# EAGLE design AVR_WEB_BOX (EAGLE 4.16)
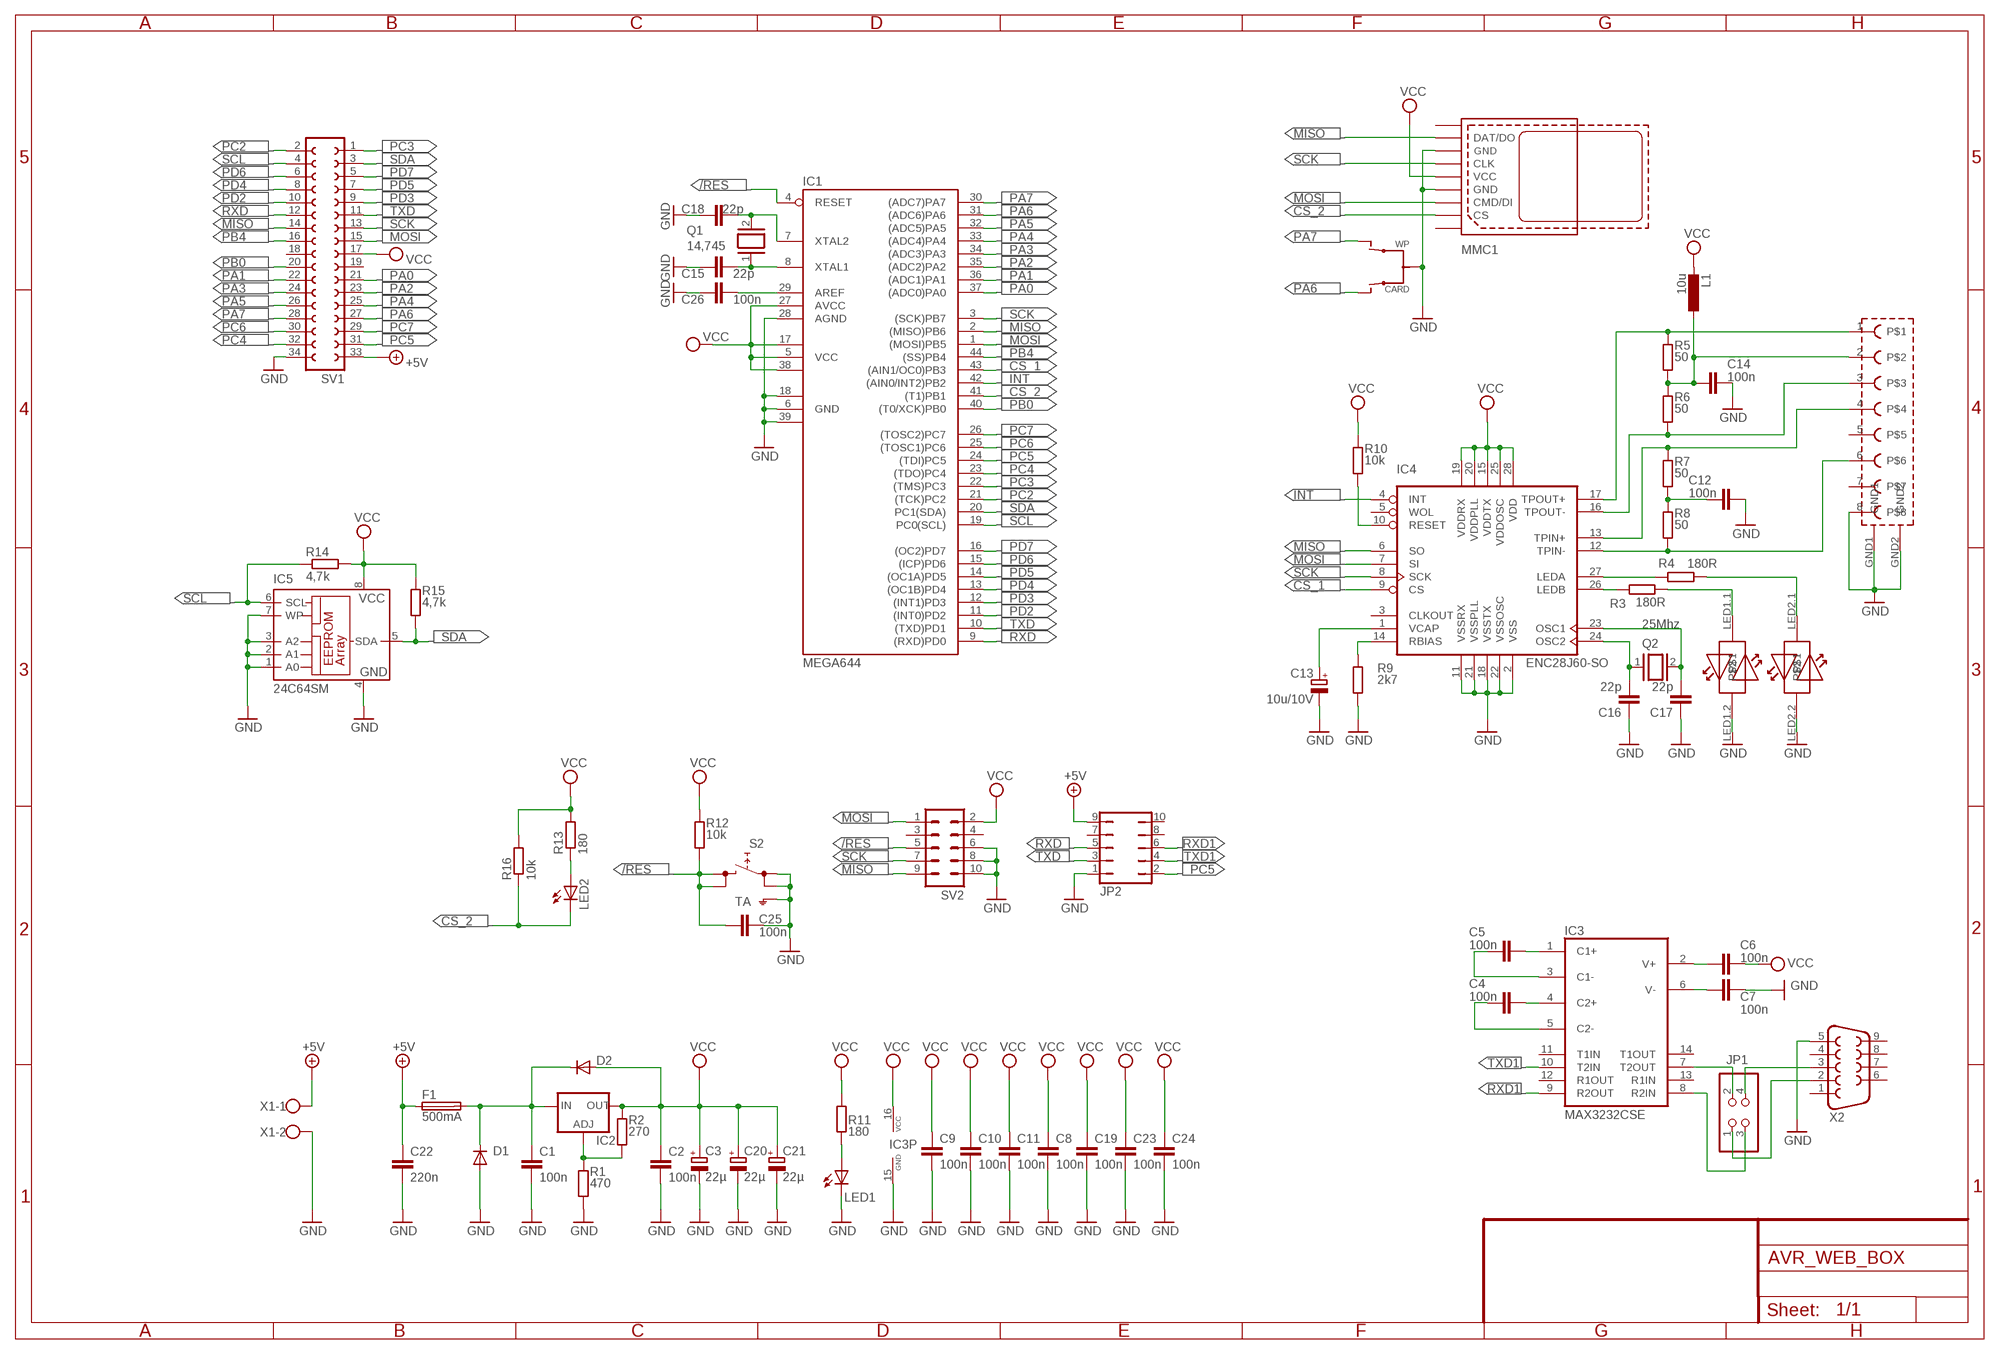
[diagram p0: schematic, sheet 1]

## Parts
C1  100n  C-EUC0805  [C0805]
C2  100n  C-EUC0805  [C0805]
C3  22µ  CPOL-EUSMCE  [SMC_E]
C4  100n  C-EUC0805  [C0805]
C5  100n  C-EUC0805  [C0805]
C6  100n  C-EUC0805  [C0805]
C7  100n  C-EUC0805  [C0805]
C8  100n  C-EUC0805  [C0805]
C9  100n  C-EUC0805  [C0805]
C10  100n  C-EUC0805  [C0805]
C11  100n  C-EUC0805  [C0805]
C12  100n  C-EUC0805  [C0805]
C13  10u/10V  CPOL-EUSMCA  [SMC_A]
C14  100n  C-EUC0805  [C0805]
C15  22p  C-EUC0805  [C0805]
C16  22p  C-EUC0805  [C0805]
C17  22p  C-EUC0805  [C0805]
C18  22p  C-EUC0805  [C0805]
C19  100n  C-EUC0805  [C0805]
C20  22µ  CPOL-EUSMCE  [SMC_E]
C21  22µ  CPOL-EUSMCE  [SMC_E]
C22  220n  C-EUC0805  [C0805]
C23  100n  C-EUC0805  [C0805]
C24  100n  C-EUC0805  [C0805]
C25  100n  C-EUC0805  [C0805]
C26  100n  C-EUC0805  [C0805]
D1  DIODE-SMB  [SMB]
D2  DIODE-SMB  [SMB]
F1  500mA  PICOFUSE  [PICOFUSE]
IC1  MEGA644  MEGA32-A  [TQFP44]
IC2  LM317TL  [317TL]
IC3  MAX3232CSE  [SO16]
IC4  ENC28J60-SO  [SO28W]
IC5  24C64SM  [SO-08M]
JP1  PINHD-2X2  [2X02]
JP2  JP5Q  [JP5Q]
L1  10u  L-EU0207/10  [0207/10]
LED1  LEDCHIP-LED0805  [CHIP-LED0805]
LED2  LEDCHIP-LED0805  [CHIP-LED0805]
MMC1  SD_CARD  [SD9]
Q1  14,745  XTAL/S  [QS]
Q2  25Mhz  XTAL/S  [QS]
R1  470  R-EU_M0805  [M0805]
R2  270  R-EU_M0805  [M0805]
R3  180R  R-EU_R0805  [R0805]
R4  180R  R-EU_R0805  [R0805]
R5  50  R-EU_R0805  [R0805]
R6  50  R-EU_R0805  [R0805]
R7  50  R-EU_R0805  [R0805]
R8  50  R-EU_R0805  [R0805]
R9  2k7  R-EU_R0805  [R0805]
R10  10k  R-EU_R0805  [R0805]
R11  180  R-EU_M0805  [M0805]
R12  10k  R-EU_M0805  [M0805]
R13  180  R-EU_M0805  [M0805]
R14  4,7k  R-EU_R0805  [R0805]
R15  4,7k  R-EU_R0805  [R0805]
R16  10k  R-EU_M0805  [M0805]
S2  TA  SKHMPSE010  [SKHMPXE010]
SV1  FE17-2W  [FE17-2W]
SV2  ML10L  [ML10L]
U$1  MAGJACK  [MAGJACK]
X1  W237-02P  [W237-132]
X2  F09HP  [F09HP]

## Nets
+5V: C22.1 F1.1 JP2.9 SV1.33 X1.1
/RES: C25.2 IC1.4(RESET) R12.1 S2.3(2.1) S2.4(2.2) SV2.5
CS_1: IC1.43((AIN1/OC0)PB3) IC4.9(CS)
CS_2: IC1.41((T1)PB1) LED2.C MMC1.7(CS) R16.1
GND: C1.2 C2.2 C3.- C7.2 C8.2 C9.2 C10.2 C11.2 C12.2 C13.- C14.2 C15.1 C16.1 C17.1 C18.1 C19.2 C20.- C21.- C22.2 C23.2 C24.2 C25.1 C26.1 D1.A IC1.6(GND) IC1.18(GND1) IC1.28(AGND) IC1.39(GND2) IC3.15(GND) IC4.2(VSS) IC4.11(VSSRX) IC4.18(VSSTX) IC4.21(VSSPLL) IC4.22(VSSOSC) IC5.1(A0) IC5.2(A1) IC5.3(A2) IC5.4(GND) IC5.7(WP) JP2.1 LED1.C MMC1.2(GND) MMC1.5(GND1) MMC1.SW1 R1.1 R9.1 S2.1(1.1) S2.2(1.2) S2.5(SH) SV1.34 SV2.6 SV2.8 SV2.10 U$1.8 U$1.GND1 U$1.GND2 U$1.LED1.2 U$1.LED2.2 X1.2 X2.5
INT: IC1.42((AIN0/INT2)PB2) IC4.4(INT)
MISO: IC1.2((MISO)PB6) IC4.6(SO) MMC1.1(DAT/DO) SV1.14 SV2.9
MOSI: IC1.1((MOSI)PB5) IC4.7(SI) MMC1.6(CMD/DI) SV1.15 SV2.1
N$1: C15.2 IC1.8(XTAL1) Q1.1
N$2: C18.2 IC1.7(XTAL2) Q1.2
N$3: C16.2 IC4.24(OSC2) Q2.1
N$5: C14.1 L1.1 R5.1 R6.2 U$1.2
N$8: LED1.A R11.1
N$9: C13.+ IC4.1(VCAP)
N$10: IC4.14(RBIAS) R9.2
N$11: C17.2 IC4.23(OSC1) Q2.2
N$12: IC2.1(ADJ) R1.2 R2.1
N$13: LED2.A R13.1
N$14: IC4.27(LEDA) R4.1
N$16: C26.2 IC1.29(AREF)
N$33: IC4.26(LEDB) R3.1
N$36: R4.2 U$1.LED2.1
N$37: IC4.10(RESET) R10.2
N$39: R3.2 U$1.LED1.1
N$40: JP1.1 X2.2
N$41: C12.1 R7.1 R8.2
N$42: IC4.12(TPIN-) R8.1 U$1.6
N$43: IC4.13(TPIN+) R7.2 U$1.4
N$44: IC4.16(TPOUT-) R6.1 U$1.3
N$45: IC4.17(TPOUT+) R5.2 U$1.1
N$49: JP1.4 X2.3
N$50: IC3.8(R2IN) JP1.3
N$51: IC3.7(T2OUT) JP1.2
N$52: C4.2 IC3.4(C2+)
N$53: C4.1 IC3.5(C2-)
N$56: C5.1 IC3.3(C1-)
N$57: C5.2 IC3.1(C1+)
N$58: C6.1 IC3.2(V+)
N$59: C7.1 IC3.6(V-)
N$250: C1.1 D1.C D2.C F1.2 IC2.3(IN)
PA0: IC1.37((ADC0)PA0) SV1.21
PA1: IC1.36((ADC1)PA1) SV1.22
PA2: IC1.35((ADC2)PA2) SV1.23
PA3: IC1.34((ADC3)PA3) SV1.24
PA4: IC1.33((ADC4)PA4) SV1.25
PA5: IC1.32((ADC5)PA5) SV1.26
PA6: IC1.31((ADC6)PA6) MMC1.SW3 SV1.27
PA7: IC1.30((ADC7)PA7) MMC1.SW2 SV1.28
PB0: IC1.40((T0/XCK)PB0) SV1.20
PB4: IC1.44((SS)PB4) SV1.16
PC2: IC1.21((TCK)PC2) SV1.2
PC3: IC1.22((TMS)PC3) SV1.1
PC4: IC1.23((TDO)PC4) SV1.32
PC5: IC1.24((TDI)PC5) JP2.2 SV1.31
PC6: IC1.25((TOSC1)PC6) SV1.30
PC7: IC1.26((TOSC2)PC7) SV1.29
PD2: IC1.11((INT0)PD2) SV1.10
PD3: IC1.12((INT1)PD3) SV1.9
PD4: IC1.13((OC1B)PD4) SV1.8
PD5: IC1.14((OC1A)PD5) SV1.7
PD6: IC1.15((ICP)PD6) SV1.6
PD7: IC1.16((OC2)PD7) SV1.5
RXD: IC1.9((RXD)PD0) JP2.5 SV1.12
RXD1: IC3.9(R2OUT) JP2.6
SCK: IC1.3((SCK)PB7) IC4.8(SCK) MMC1.3(CLK) SV1.13 SV2.7
SCL: IC1.19(PC0(SCL)) IC5.6(SCL) R14.1 SV1.4
SDA: IC1.20(PC1(SDA)) IC5.5(SDA) R15.1 SV1.3
TXD: IC1.10((TXD)PD1) JP2.3 SV1.11
TXD1: IC3.10(T2IN) JP2.4
VCC: C2.1 C3.+ C6.2 C8.1 C9.1 C10.1 C11.1 C19.1 C20.+ C21.+ C23.1 C24.1 D2.A IC1.5(VCC) IC1.17(VCC1) IC1.27(AVCC) IC1.38(VCC2) IC2.2(OUT) IC3.16(VCC) IC4.15(VDDTX) IC4.19(VDDRX) IC4.20(VDDPLL) IC4.25(VDDOSC) IC4.28(VDD) IC5.8(VCC) L1.2 MMC1.4(VCC) R2.2 R10.1 R11.2 R12.2 R13.2 R14.2 R15.2 R16.2 SV1.17 SV2.2
Unconnected: IC3.11(T1IN) IC3.12(R1OUT) IC3.13(R1IN) IC3.14(T1OUT) IC4.3(CLKOUT) IC4.5(WOL) JP2.7 JP2.8 JP2.10 MMC1.8(DAT1/RSV:8) MMC1.9(DAT2/RSV:9) SV1.18 SV1.19 SV2.3 SV2.4 U$1.5 U$1.7 X2.1 X2.4 X2.6 X2.7 X2.8 X2.9

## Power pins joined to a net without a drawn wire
GND1: MMC1.G1(GND1)
GND2: MMC1.G2(GND2)
GND3: MMC1.G3(GND3)
GND4: MMC1.G4(GND4)
GND5: MMC1.G5(GND5)
GND6: MMC1.G6(GND6)
GND7: MMC1.G7(GND7)

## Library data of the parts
C1 C2 C4-C12 C14-C19 C22-C26 = rcl:C-EU: CAPACITOR, European symbol
C3 C13 C20 C21 = rcl:CPOL-EU: POLARIZED CAPACITOR, European symbol
D1 D2 = diode:DIODE-: DIODE
F1 = fuse:PICOFUSE: PICOFUSE
IC1 = avr:MEGA32: MICROCONTROLLER 32 Kbytes FLASH 2 Kbytes SRAM 1 Kbytes EEPROM USART 8-channel 10 bit ADC
IC2 = v-reg:LM317TL: VOLTAGE REGULATOR
IC3 = maxim:MAX3232*: True RS-232 Transceivers 3.0V to 5.5V, Low-Power up to 1Mbps, Using Four 0.1µF External Capacitors Source: http://pdfserv.maxim-ic.com/en/ds/MAX3222-MAX3241.pdf
IC4 = microchip-enc28j60:ENC28J60-*: Microchip 10Mbit Eth. contoller with SPI interface
IC5 = microchip:24*: Serial EEPROM I2C
JP1 = pinhead:PINHD-2X2: PIN HEADER
JP2 = jumper:JP5Q: JUMPER
L1 = rcl:L-EU: INDUCTOR, European symbol
LED1 LED2 = led:LED: LED
MMC1 = sd_card:SD_CARD: Farnell / Order Code: 4381610 http://www.farnell.com/datasheets/37839.pdf kingfont Precision Industrial co., LTD. Secure Digital Memory Card Push-Push connector type B Changes by Guido Fischer - 29.12.2004 www.ispf.de by André Mansur - Brazil - 19/11/2004
Q1 Q2 = special:XTAL/S: CRYSTAL
R1-R16 = rcl:R-EU_: RESISTOR, European symbol
S2 = switch:SKHMP*E010: 6.2 X 6.5mm TACT Switch (SMD) Source: http://www3.alps.co.jp/WebObjects/catalog.woa/PDF/E/Switch/Tact/SKHM/SKHM.PDF
SV1 = con-lsta:FE17-2W: FEMALE HEADER
SV2 = con-harting-ml:ML10: HARTING
U$1 = magjacksmalldrill:MAGJACK
X1 = con-wago-508:W237-02P: WAGO SREW CLAMP
X2 = con-subd:F09: SUB-D

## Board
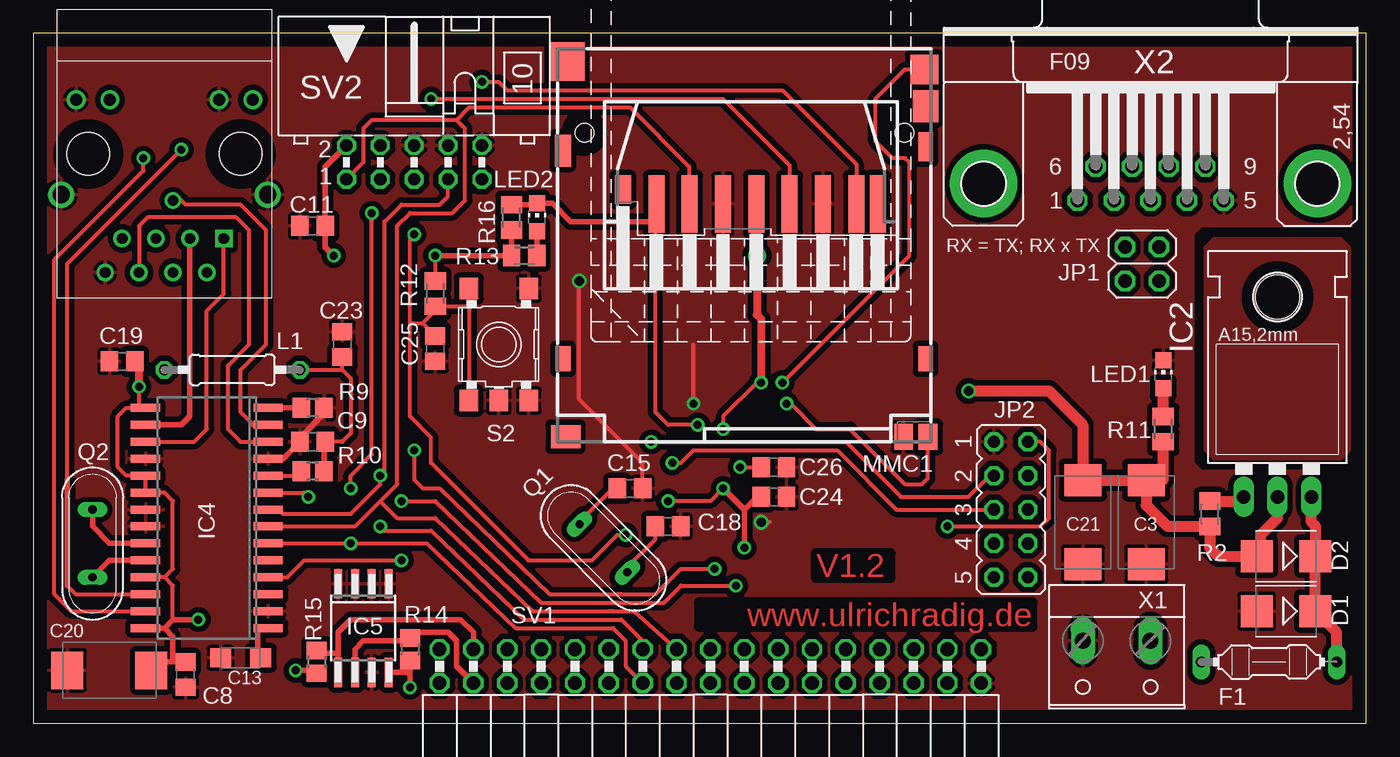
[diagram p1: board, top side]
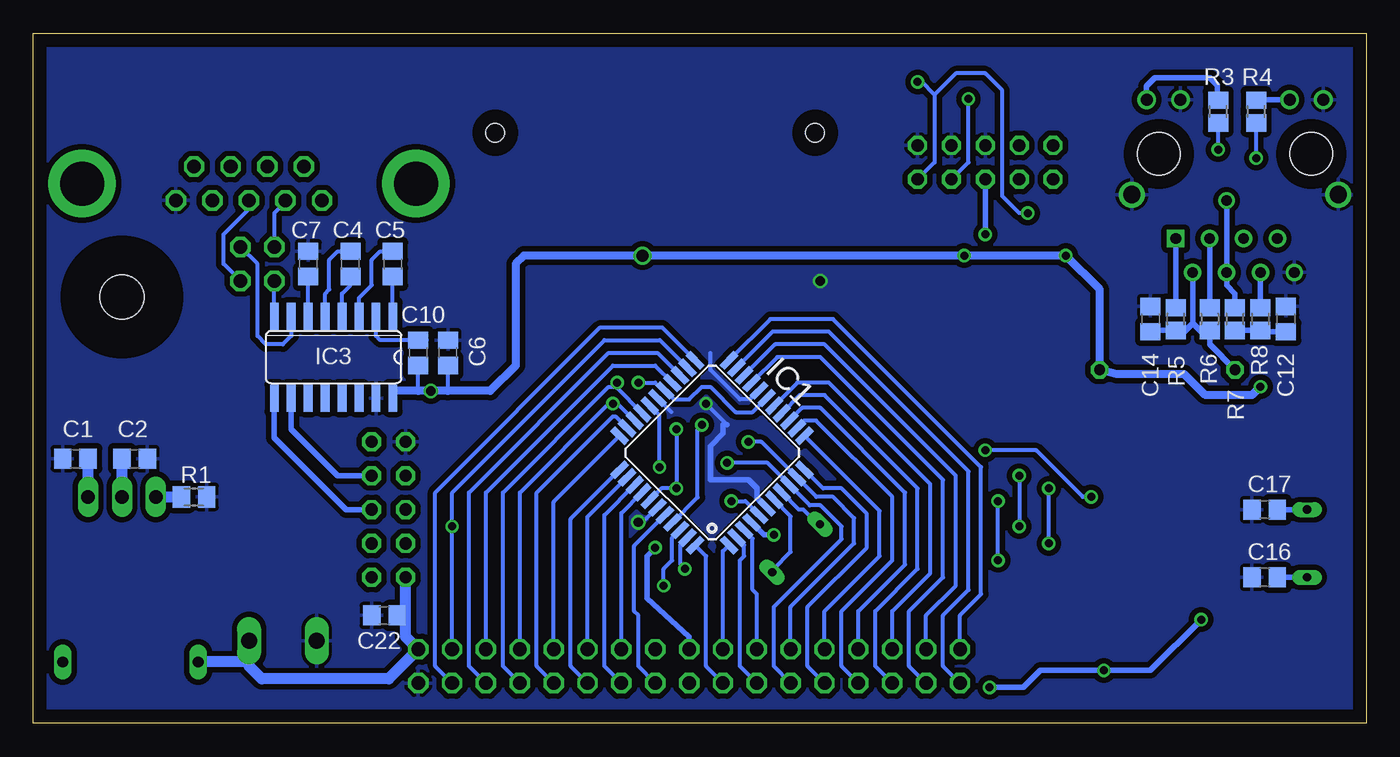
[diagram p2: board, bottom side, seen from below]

Size 99.99 x 51.74 mm. Coordinates in mm from the lower left corner, seen from the top.
Outline: 0,0 99.99,0 99.99,51.74 0,51.74 0,0
Copper layers (1*16): Top 0.035mm / dielectric 1.5mm / Bottom 0.035mm
Design rules "default": minimum track width 10mil, minimum drill 24mil, track to track 8mil, track to pad 8mil, pad to pad 8mil, via to via 8mil, smd to smd 8mil, copper to edge 40mil, drill to drill 8mil, minimum pad ring 10mil, minimum via ring 8mil, stop-mask expansion 4mil, vias tented up to drill 0mil, thermal gap 10mil

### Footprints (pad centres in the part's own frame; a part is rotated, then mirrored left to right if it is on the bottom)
C0805 = smd 1.3 x 1.5: 1 -0.95,0; 2 0.95,0
SMC_E = smd 2.4 x 2.8: + -3.15,0; - 3.15,0
SMC_A = smd 1.6 x 1.4: + -1.5,0; - 1.5,0
SMB = smd 2.4 x 2.4: A 2.2,0; C -2.2,0
PICOFUSE = drill 0.813 long: 1 -5.08,0; 2 5.08,0
TQFP44 = smd 1.5 x 0.5: 1 -5.8,4; 2 -5.8,3.2; 3 -5.8,2.4; 4 -5.8,1.6; 5 -5.8,0.8; 6 -5.8,0; 7 -5.8,-0.8; 8 -5.8,-1.6; 9 -5.8,-2.4; 10 -5.8,-3.2; 11 -5.8,-4; 23 5.8,-4; 24 5.8,-3.2; 25 5.8,-2.4; 26 5.8,-1.6; 27 5.8,-0.8; 28 5.8,0; 29 5.8,0.8; 30 5.8,1.6; 31 5.8,2.4; 32 5.8,3.2; 33 5.8,4 | smd 0.5 x 1.5: 12 -4,-5.8; 13 -3.2,-5.8; 14 -2.4,-5.8; 15 -1.6,-5.8; 16 -0.8,-5.8; 17 0,-5.8; 18 0.8,-5.8; 19 1.6,-5.8; 20 2.4,-5.8; 21 3.2,-5.8; 22 4,-5.8; 34 4,5.8; 35 3.2,5.8; 36 2.4,5.8; 37 1.6,5.8; 38 0.8,5.8; 39 0,5.8; 40 -0.8,5.8; 41 -1.6,5.8; 42 -2.4,5.8; 43 -3.2,5.8; 44 -4,5.8
317TL = drill 1.016 long: 1 -2.54,-3.81; 2 0,-3.81; 3 2.54,-3.81 | hole 3.302: 0,11.176
SO16 = smd 0.66 x 2.032: 1 -4.445,-3.073; 2 -3.175,-3.073; 3 -1.905,-3.073; 4 -0.635,-3.073; 5 0.635,-3.073; 6 1.905,-3.073; 7 3.175,-3.073; 8 4.445,-3.073; 9 4.445,3.073; 10 3.175,3.073; 11 1.905,3.073; 12 0.635,3.073; 13 -0.635,3.073; 14 -1.905,3.073; 15 -3.175,3.073; 16 -4.445,3.073
SO28W = smd 0.6 x 2.2: 1 -8.255,-4.6; 2 -6.985,-4.6; 3 -5.715,-4.6; 4 -4.445,-4.6; 5 -3.175,-4.6; 6 -1.905,-4.6; 7 -0.635,-4.6; 8 0.635,-4.6; 9 1.905,-4.6; 10 3.175,-4.6; 11 4.445,-4.6; 12 5.715,-4.6; 13 6.985,-4.6; 14 8.255,-4.6; 15 8.255,4.6; 16 6.985,4.6; 17 5.715,4.6; 18 4.445,4.6; 19 3.175,4.6; 20 1.905,4.6; 21 0.635,4.6; 22 -0.635,4.6; 23 -1.905,4.6; 24 -3.175,4.6; 25 -4.445,4.6; 26 -5.715,4.6; 27 -6.985,4.6; 28 -8.255,4.6
SO-08M = smd 0.6 x 2.2: 1 -1.905,-3.33; 2 -0.635,-3.33; 3 0.635,-3.33; 4 1.905,-3.33; 5 1.905,3.33; 6 0.635,3.33; 7 -0.635,3.33; 8 -1.905,3.33
2X02 = drill 1.016 octagon: 1 -1.27,-1.27; 2 -1.27,1.27; 3 1.27,-1.27; 4 1.27,1.27
JP5Q = drill 0.914 octagon: 1 -5.08,-1.27; 2 -5.08,1.27; 3 -2.54,-1.27; 4 -2.54,1.27; 5 0,-1.27; 6 0,1.27; 7 2.54,-1.27; 8 2.54,1.27; 9 5.08,-1.27; 10 5.08,1.27
0207/10 = drill 0.813 octagon: 1 -5.08,0; 2 5.08,0
CHIP-LED0805 = smd 1.2 x 1.2: A 0,-1.05; C 0,1.05
SD9 = smd 1.2 x 4.3: 1 -8.4,5.34; 2 -5.9,5.34; 3 -3.4,5.34; 4 -0.9,5.34; 5 1.6,5.34; 6 4.1,5.34; 7 6.6,5.34; 8 -10.025,5.34 | smd 1.2 x 2.15: 9 9.1,4.265 | smd 1.9 x 2.4: G1 -13.6,-2 | smd 1.1 x 2.2: G2 -13.6,1.05 | smd 1.1 x 1.9: G3 -13.6,16.95; G5 13.6,16.95 | smd 2.2 x 1.75: G4 13.4,22.8 | smd 1.2 x 2.4: G6 13.6,1.35 | smd 2.6 x 2.9: G7 13.3,-5.35 | smd 1.4 x 1.95: SW1 -11.95,22.8 | smd 2.1 x 2.2: SW2 -13.5,-4.75 | smd 1.45 x 1.95: SW3 -13.775,22.8 | hole 1.4: -12,0; 12,0
QS = drill 0.61 long: 1 -2.54,0; 2 2.54,0
M0805 = smd 1.3 x 1.6: 1 -0.95,0; 2 0.95,0
R0805 = smd 1.3 x 1.5: 1 -0.85,0; 2 0.85,0
SKHMPXE010 = smd 1.6 x 1.4: 1 -4.2,2.25; 2 4.2,2.25; 3 -4.2,-2.25; 4 4.2,-2.25; 5 4.2,0
FE17-2W = drill 1.016 octagon: 1 -20.32,1.27; 2 -20.32,-1.27; 3 -17.78,1.27; 4 -17.78,-1.27; 5 -15.24,1.27; 6 -15.24,-1.27; 7 -12.7,1.27; 8 -12.7,-1.27; 9 -10.16,1.27; 10 -10.16,-1.27; 11 -7.62,1.27; 12 -7.62,-1.27; 13 -5.08,1.27; 14 -5.08,-1.27; 15 -2.54,1.27; 16 -2.54,-1.27; 17 0,1.27; 18 0,-1.27; 19 2.54,1.27; 20 2.54,-1.27; 21 5.08,1.27; 22 5.08,-1.27; 23 7.62,1.27; 24 7.62,-1.27; 25 10.16,1.27; 26 10.16,-1.27; 27 12.7,1.27; 28 12.7,-1.27; 29 15.24,1.27; 30 15.24,-1.27; 31 17.78,1.27; 32 17.78,-1.27; 33 20.32,1.27; 34 20.32,-1.27
ML10L = drill 0.914 octagon: 1 -5.08,-1.27; 2 -5.08,1.27; 3 -2.54,-1.27; 4 -2.54,1.27; 5 0,-1.27; 6 0,1.27; 7 2.54,-1.27; 8 2.54,1.27; 9 5.08,-1.27; 10 5.08,1.27
MAGJACK = drill 0.8 square: 1 -4.445,6.35 | drill 0.8 round: 2 -3.175,8.89; 3 -1.905,6.35; 4 -0.635,8.89; 5 0.635,6.35; 6 1.905,8.89; 7 3.175,6.35; 8 4.445,8.89 | drill 1.3 round: GND1 -7.747,3.048; GND2 7.747,3.048 | drill 0.9 round: LED1.1 -6.629,-4.064; LED1.2 -4.089,-4.064; LED2.1 4.089,-4.064; LED2.2 6.629,-4.064 | hole 3.2: -5.715,0; 5.715,0
W237-132 = drill 1.194 long: 1 -2.54,-0.635; 2 2.54,-0.635
F09HP = drill 1.016 octagon: 1 -5.486,-1.27; 2 -2.743,-1.27; 3 0,-1.27; 4 2.743,-1.27; 5 5.486,-1.27; 6 -4.115,1.27; 7 -1.372,1.27; 8 1.372,1.27; 9 4.115,1.27 | drill 3.302 pad 5.08 round: G1 -12.522,0; G2 12.522,0

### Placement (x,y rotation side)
C1  96.83,19.84 180 bottom
C2  92.39,19.84 0 bottom
C3  83.5,15.07 270 top
C4  76.2,34.44 270 bottom
C5  73.02,34.44 270 bottom
C6  71.12,27.77 270 bottom
C7  79.37,34.44 90 bottom
C8  11.42,3.65 270 top
C9  20.95,21.11 180 top
C10  68.89,27.77 90 bottom
C11  20.95,37.3 180 top
C12  6.03,30.32 90 bottom
C13  15.55,4.92 180 top
C14  16.19,30.32 90 bottom
C15  44.76,17.61 180 top
C16  7.62,10.95 0 bottom
C17  7.62,16.03 0 bottom
C18  47.62,14.76 180 top
C19  6.66,27.14 180 top
C20  5.71,3.96 180 top
C21  78.73,15.07 270 top
C22  73.66,8.09 180 bottom
C23  23.17,28.41 90 top
C24  55.56,16.98 0 top
C25  30.16,28.09 90 top
C26  55.56,19.2 180 top
D1  93.98,8.41 180 top
D2  93.98,12.54 180 top
F1  92.7,4.6 0 top
IC1  49.08,20.29 135 bottom
IC2  93.34,20.79 0 top
IC3  77.47,27.46 180 bottom
IC4  13.01,15.39 90 top
IC5  24.76,7.14 180 top
JP1  83.18,34.44 270 top
JP2  73.34,16.03 270 top
L1  14.92,26.5 0 top
LED1  84.77,26.19 0 top
LED2  37.78,37.94 0 top
MMC1  53.34,44.29 180 top
Q1  42.76,13.13 315 top
Q2  4.44,13.49 90 top
R1  87.94,16.98 180 bottom
R2  88.26,15.71 270 top
R3  11.11,45.87 90 bottom
R4  8.25,45.87 90 bottom
R5  14.28,30.32 90 bottom
R6  11.74,30.32 270 bottom
R7  9.84,30.32 90 bottom
R8  7.93,30.32 270 bottom
R9  20.95,23.65 180 top
R10  20.95,18.89 180 top
R11  84.77,22.06 270 top
R12  30.16,32.22 90 top
R13  36.82,35.08 180 top
R14  28.25,5.55 270 top
R15  21.27,4.6 270 top
R16  35.87,37.94 270 top
S2  34.92,28.41 270 top
SV1  50.79,4.28 0 top
SV2  28.57,42.06 0 top
U$1  9.84,42.7 180 top
X1  81.28,5.55 180 top
X2  83.81,40.48 0 top

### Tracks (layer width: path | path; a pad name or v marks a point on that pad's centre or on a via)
+5V
  Bottom 0.813: 72.07,8.09 72.07,6.5 SV1.33 73.34,3.33 82.86,3.33 83.81,4.28 83.81,4.6 | 72.07,8.09 JP2.9 | 72.07,8.09 C22.1 | 83.81,4.6 F1.1 | 83.81,4.6 X1.1
/RES  (via drill 0.6)
  Top 0.305: v44.45,14.12 43.81,14.12 41.9,12.22 37.14,12.22 29.84,19.52 29.84,21.43 28.25,23.01 28.25,30 | v28.57,36.67 28.25,36.35 28.25,30 | S2.3 32.7,32.58 32.7,31.27 | S2.4 32.7,24.24 32.7,31.27 | C25.2 29.21,30 | 29.21,30 30.16,30.95 R12.1 32.7,31.27 | 28.25,30 29.21,30
  Bottom 0.406: IC1.4 45.17,14.12 v44.45,14.12 | v28.57,36.67 SV2.5
CS_1  (via drill 0.6)
  Top 0.305: IC4.9 20.32,17.3 v20.63,16.98 | v28.57,20.47 28.57,18.25 29.21,17.61 30.48,17.61 38.73,9.68 44.13,9.68 | 44.13,9.68 43.81,9.68 | 44.13,9.68 46.67,9.68 48.57,11.58 v51.11,11.58
  Bottom 0.305: v20.63,16.98 21.27,16.98 24.76,20.47 v28.57,20.47 | IC1.43 51.43,13.41 51.43,11.9 v51.11,11.58
CS_2  (via drill 0.6)
  Top 0.305: 49.52,22.38 47.62,22.38 46.67,23.33 46.67,37.62 | 46.67,38.88 MMC1.7
  Top 0.406: v49.84,22.38 49.52,22.38 | 46.67,38.88 46.67,37.62 40.32,37.62 38.95,38.99 LED2.C 37.78,38.89 R16.1
  Bottom 0.305: IC1.41 50.16,16.94 50.16,22.06 v49.84,22.38
GND  (via drill 0.6, 0.7)
  Top 0.305: v54.6,15.07 55.24,15.07 | v49.52,23.96 49.52,28.41 | C15.1 45.71,19.52 40.95,24.28 v40.95,33.17
  Top 0.406: R9.1 21.8,23.43 21.9,23.33 20,21.43 C9.2 18.73,19.84 IC4.11
  Bottom 0.305: IC1.39 54.29,15.07 v54.6,15.07 | IC1.28 52.12,23.33 | IC1.18 46.21,24.28 46.98,24.28 49.21,26.5 49.21,27.77 | 47.94,22.38 v49.52,23.96 | v40.95,33.17 40.63,33.17
  Bottom 0.406: IC1.6 45.71,16.93 C15.1 46.35,18.25 49.21,18.25 49.21,20.79 48.25,21.74 48.25,22.38 47.94,22.38
  pour Top (isolate 0.406): -0.01,51.59 100.01,51.59 100.01,37.3 87.62,37.3 86.99,36.67 86.99,19.52 87.62,18.89 100.01,18.89 100.01,0.15 -0.01,0.15
  pour Bottom (isolate 0.406): -0.01,51.59 -0.01,0.15 100.01,0.15 100.01,51.59
INT  (via drill 0.6)
  Top 0.305: IC4.4 19.05,10.95 20.32,12.22 v27.62,12.22 | v27.62,16.66 30.16,16.66 38.09,9.04 43.81,9.04 | 43.81,9.04 43.49,9.04 | 43.81,9.04 47.3,9.04 48.57,10.31 v52.7,10.31
  Bottom 0.305: v27.62,12.22 v27.62,16.66 | IC1.42 52.06,13.9 52.06,12.22 52.7,11.58 v52.7,10.31
MISO  (via drill 0.6)
  Top 0.305: MMC1.1 61.73,41.92 56.19,47.46 35.55,47.46 34.92,48.1 v33.65,48.1 | IC4.6 v23.81,13.49 29.52,13.49 36.19,7.14 43.49,7.14 44.45,6.18 44.45,4.28 SV1.14 | v25.39,38.25 25.39,20.16 23.81,18.57 v23.81,17.61
  Bottom 0.305: IC1.2 46.67,13.35 46.67,12.54 46.98,12.22 46.98,4.28 SV1.14 | v33.65,48.1 33.33,48.1 32.38,47.14 | 32.38,47.14 32.38,42.06 SV2.9 | v25.39,38.25 26.03,38.25 27.3,39.52 27.3,47.46 28.57,48.73 30.79,48.73 32.38,47.14 | v23.81,13.49 v23.81,17.61 v23.81,13.49
MOSI
  Top 0.305: MMC1.6 49.23,38.92 49.21,38.89 49.21,41.75 44.76,46.19 32.7,46.19 31.75,45.24 | IC4.7 24.12,14.76 26.03,16.66 | 26.03,16.66 27.3,17.93 27.3,37.3 28.25,38.25 31.43,38.25 32.38,39.21 32.38,44.6 31.75,45.24 | 26.03,16.66 27.3,15.39 30.16,15.39 37.46,8.41 43.49,8.41 | 43.49,8.41 43.17,8.41 | 43.49,8.41 45.08,8.41 SV1.15 48.25,4.6 | 31.75,45.24 25.39,45.24 24.76,44.6 24.76,42.06 SV2.1
  Bottom 0.305: IC1.1 48.25,12.91 SV1.15
N$1
  Top 0.305: Q1.1 40.97,15.06 40.95,15.07 43.49,17.61 C15.2
  Bottom 0.305: IC1.8 42.55,16.03 42.22,16.03 40.95,14.76 40.95,14.91 Q1.1
N$2
  Top 0.305: Q1.2 44.56,11.47 44.45,11.58 46.67,13.81 C18.2
  Bottom 0.305: IC1.7 43.17,15.52 43.17,12.85 44.45,11.58 44.45,11.27 44.49,11.27 Q1.2
N$3
  Top 0.406: IC4.24 5.71,12.22 Q2.1
  Bottom 0.406: Q2.1 C16.2
N$5
  Bottom 0.406: 13.01,30 U$1.2 | 13.01,30 12.38,29.36 11.74,29.36 | 11.74,29.36 R6.2 | 13.01,30 13.65,29.36 14.28,29.36 R5.1 16.09,29.46 C14.1 | 11.74,29.36 11.74,28.41 L1.1
N$8
  Top 0.813: R11.1 LED1.A
N$9
  Top 0.406: C13.+ 16.82,4.92 16.82,7.14 IC4.1
N$10
  Top 0.406: IC4.14 R9.2
N$11
  Top 0.406: IC4.23 5.71,13.49 4.44,14.76 Q2.2
  Bottom 0.406: Q2.2 C17.2
N$12
  Top 0.813: R2.1 90.48,16.66 IC2.1
  Bottom 0.813: IC2.1 R1.2
N$13
  Top 0.406: LED2.A 37.78,36.98 37.77,36.98 R13.1
N$14  (via drill 0.6)
  Top 0.305: IC4.27 2.85,8.41 1.58,9.68 1.58,34.76 8.25,41.43 v8.25,42.38
  Bottom 0.305: v8.25,42.38 R4.1
N$15
  pour Top: 87.94,35.71 88.58,36.35 98.1,36.35 98.74,35.71 98.74,20.47 98.1,19.84 88.58,19.84 87.94,20.47
N$16  (via drill 0.6)
  Top 0.305: v53.02,19.2 C26.2
  Bottom 0.305: IC1.29 53.02,23.1 v53.02,19.2
N$33  (via drill 0.6)
  Top 0.305: IC4.26 3.17,9.68 2.54,10.31 | v11.11,43.01 2.54,34.44 2.54,18.25
  Top 0.406: 2.54,10.31 2.54,18.25
  Bottom 0.305: v11.11,43.01 R3.1
N$36
  Bottom 0.406: R4.2 8.03,46.72 7.93,46.82 7.87,46.76 U$1.LED2.1
N$37
  Top 0.305: IC4.10 19.68,18.57 R10.2
N$39
  Bottom 0.406: R3.2 11.11,46.82 11.17,46.76 11.17,47.84 11.74,48.41 15.87,48.41 16.51,47.78 16.51,46.82 16.47,46.79 U$1.LED1.1
N$40
  Bottom 0.305: X2.2 80.96,39.21 81.91,38.25 JP1.1
N$41
  Bottom 0.406: C12.1 7.93,29.36 R8.2 9.73,29.46 9.84,29.36 R7.1
N$42
  Top 0.305: IC4.12 15.55,21.11 14.6,22.06 14.6,26.82 16.19,28.41 16.19,36.98 15.23,37.93 8.57,37.93 7.93,37.3 U$1.6
  Bottom 0.406: U$1.6 R8.1
N$43  (via drill 0.8)
  Top 0.305: 16.51,22.38 15.55,23.33 15.55,26.5 17.46,28.41 17.46,36.98 15.55,38.89 11.42,38.89 11.11,39.21 v10.47,39.21
  Top 0.406: IC4.13 16.51,22.38
  Bottom 0.406: R7.2 9.84,32.22 10.47,32.86 U$1.4 v10.47,39.21
N$44
  Top 0.406: IC4.16 11.11,22.38 11.74,23.01 U$1.3
  Bottom 0.406: U$1.3 R6.1
N$45
  Top 0.305: IC4.17 12.06,21.11 13.01,22.06 13.01,30.95 14.28,32.22 U$1.1
  Bottom 0.406: U$1.1 R5.2
N$49
  Bottom 0.305: X2.3 83.81,38.57 85.72,36.67 85.72,34.44 JP1.4
N$50
  Bottom 0.305: IC3.8 JP1.3
N$51
  Bottom 0.305: IC3.7 80.64,29.04 81.28,28.41 82.55,28.41 83.18,29.04 83.18,34.44 JP1.2
N$52
  Bottom 0.305: C4.2 76.2,32.86 76.83,32.22 IC3.4
N$53
  Bottom 0.305: C4.1 77.15,35.39 77.78,34.76 77.78,32.54 78.1,32.22 IC3.5
N$56
  Bottom 0.305: C5.1 73.98,35.39 74.61,34.76 74.61,32.86 75.56,31.9 IC3.3
N$57
  Bottom 0.305: IC3.1 C5.2
N$58
  Bottom 0.305: C6.1 70.48,28.73 73.97,28.73 74.29,29.04 IC3.2 74.29,30.63
N$59
  Bottom 0.305: IC3.6 C7.1
N$250
  Top 0.305: 96.2,8.41 D1.C
  Top 0.813: F1.2 97.79,6.82 96.2,8.41 | D1.C 96.18,12.51 | IC2.3 95.88,15.07 96.2,14.76 96.2,12.54
  Top 1.27: 96.18,12.51 96.2,12.54 D2.C
  Bottom 0.305: C1.1
  Bottom 0.813: IC2.3 C1.1
PA0
  Bottom 0.305: IC1.37 55.88,15.75 SV1.21
PA1
  Bottom 0.305: IC1.36 57.14,15.61 57.14,4.28 SV1.22
PA2
  Bottom 0.305: IC1.35 58.41,15.47 SV1.23
PA3
  Bottom 0.305: IC1.34 59.68,15.33 59.68,4.28 SV1.24
PA4
  Bottom 0.305: IC1.33 60.95,16.61 SV1.25
PA5
  Bottom 0.305: IC1.32 56.33,23.01 56.51,23.01 62.22,17.3 62.22,4.28 SV1.26
PA6  (via drill 0.6)
  Top 0.305: MMC1.SW3 67.11,18.37 66.67,17.93 65.4,17.93 61.27,22.06 58.73,22.06 56.83,23.96 v56.51,23.96
  Bottom 0.305: IC1.31 56.15,23.96 v56.51,23.96 56.83,23.96 63.49,17.3 SV1.27
PA7  (via drill 0.6)
  Top 0.305: MMC1.SW2 65.39,49.04 63.18,46.82 63.18,43.65 64.45,42.38 65.4,42.38 65.72,42.06 65.72,35.08 v56.19,25.55
  Bottom 0.305: IC1.30 56.29,25.23 56.51,25.23 | SV1.28 64.77,4.28 64.77,17.3 56.83,25.23 56.51,25.23 | 56.51,25.23 v56.19,25.55
PB0
  Bottom 0.305: IC1.40 54.92,13.31 54.92,8.41 54.6,8.09 54.6,4.28 SV1.20
PB4
  Bottom 0.305: IC1.44 49.52,12.53 49.52,4.28 SV1.16
PC2
  Bottom 0.305: IC1.21 44.53,29.36 40.32,29.36 29.84,18.89 29.84,9.99 31.75,8.09 31.75,4.28 SV1.2
PC3
  Bottom 0.305: IC1.22 44.7,30.32 40,30.32 28.89,19.2 28.89,9.68 30.48,8.09 SV1.1
PC4
  Bottom 0.305: IC1.23 52.81,29.68 57.46,29.68 69.84,17.3 69.84,4.28 SV1.32
PC5  (via drill 0.6)
  Top 0.305: JP2.2 75.56,21.11 76.2,20.47 76.2,15.39 75.56,14.76 v68.58,14.76
  Bottom 0.305: IC1.24 52.99,28.73 57.14,28.73 68.58,17.3 v68.58,14.76 SV1.31
PC6
  Bottom 0.305: IC1.25 53.17,27.77 56.83,27.77 67.31,17.3 67.31,4.28 SV1.30
PC7
  Bottom 0.305: IC1.26 53.35,26.82 56.51,26.82 66.04,17.3 SV1.29
PD2
  Bottom 0.305: IC1.11 40.75,17.61 39.36,17.61 37.46,15.71 37.46,13.17 41.9,8.72 41.9,4.28 SV1.10
PD3
  Bottom 0.305: IC1.12 36.51,15.92 36.51,12.54 40.63,8.41 SV1.9
PD4
  Bottom 0.305: IC1.13 42.14,22.7 41.27,22.7 35.55,16.98 35.55,12.22 39.36,8.41 39.36,4.28 SV1.8
PD5
  Bottom 0.305: IC1.14 42.32,23.65 40.95,23.65 34.6,17.3 34.6,11.9 38.09,8.41 SV1.7
PD6
  Bottom 0.305: IC1.15 42.5,24.6 40.63,24.6 33.65,17.61 33.65,11.58 36.82,8.41 36.82,4.28 SV1.6
PD7
  Bottom 0.305: IC1.16 42.68,25.55 40.32,25.55 32.7,17.93 32.7,11.27 35.55,8.41 SV1.5
RXD  (via drill 0.6)
  Top 0.305: v47.94,19.52 48.57,19.52 49.52,20.47 60.32,20.47 64.77,16.03 JP2.5
  Bottom 0.305: SV1.12 44.45,4.28 44.45,8.72 39.36,13.8 39.36,14.76 40.95,16.34 41.74,16.34 IC1.9 44.91,19.52 v47.94,19.52
RXD1
  Bottom 0.406: JP2.6 76.51,16.03 81.91,21.43 IC3.9
SCK  (via drill 0.6)
  Top 0.305: MMC1.3 56.73,41.84 51.75,46.82 v29.84,46.82 | IC4.8 18.41,16.03 18.73,15.71 23.81,15.71 26.03,17.93 v26.03,18.57 26.35,18.89 26.35,37.62 27.62,38.89 30.48,38.89 31.11,39.52 SV2.7 | v26.03,14.76 26.35,14.44 29.84,14.44 36.82,7.77 44.13,7.77 45.71,6.18 SV1.13
  Bottom 0.305: IC1.3 46.03,13.85 46.03,9.99 45.71,9.68 SV1.13 | v26.03,18.57 v26.03,14.76 | v29.84,46.82 29.84,42.06 SV2.7
SCL
  Top 0.406: IC5.6 24.12,5.55 24.76,6.18 27.62,6.18 28.25,6.82 | SV1.4 31.75,4.28 31.75,6.18 31.11,6.82 28.25,6.82 | 28.25,6.82 R14.1
  Bottom 0.305: IC1.19 44.17,27.46 40.95,27.46 31.75,18.25 31.75,10.95 34.28,8.41 34.28,4.28 SV1.4
SDA
  Top 0.406: 22.86,5.23 IC5.5 | 22.86,5.23 22.86,6.82 23.81,7.77 32.06,7.77 33.02,6.82 SV1.3 | R15.1 21.48,5.13 21.27,5.23 22.86,5.23
  Bottom 0.305: IC1.20 44.35,28.41 40.63,28.41 30.79,18.57 30.79,10.31 33.02,8.09 SV1.3
TXD  (via drill 0.6)
  Top 0.305: v46.35,21.11 60.95,21.11 65.08,16.98 70.16,16.98 71.75,18.57 JP2.3
  Bottom 0.305: SV1.11 43.17,8.72 38.41,13.49 38.41,15.39 40,16.98 41.24,16.98 IC1.10 45.37,21.11 v46.35,21.11
TXD1
  Bottom 0.406: IC3.10 80.64,22.06 77.15,18.57 JP2.4
VCC  (via drill 0.6, 0.7, 0.9)
  Top 0.305: 8.25,17.3 8.41,17.46 IC4.19 6.98,18.57 6.34,19.2 6.34,23.01 6.98,23.65 7.93,23.65 | 10.47,7.77 10.47,10.31 9.84,10.95 | 8.25,10.95 IC4.25 9.84,10.95 | 9.84,10.95 10.47,11.58 10.47,16.66 9.84,17.3 8.25,17.3 | 8.25,17.3 IC4.20 | 7.93,23.65 IC4.15 | 7.93,23.65 v7.93,25.23 | C20.+ 7.93,3.96 8.57,4.6 | v47.62,16.66 50.79,16.66 v51.75,17.61 52.38,16.98 | C3.+ 84.77,18.25 84.74,18.23 | 10.47,4.6 C8.1 | 7.93,27.14 C19.1 | v30.16,35.08 R12.2 | C9.1 23.17,21.11 23.81,21.74 23.81,25.87 23.17,26.5 | 23.17,26.5 C23.1 | L1.2 23.17,26.5 | v51.75,22.06 51.75,23.01 54.29,25.55 v54.6,25.55 | 54.29,16.98 C24.1
  Top 0.406: R13.2 36.19,35.08 | v30.16,35.08 R13.2 | IC5.8 28.09,3.81 28.25,3.65 v28.25,2.69 R14.2 | v12.38,7.77 10.47,7.77 9.84,7.14 | R15.2 21.59,3.96 v19.68,3.96 | 10.47,4.6 9.52,4.6 8.57,4.6 | C8.1 10.47,4.59 10.47,4.6 | 10.47,4.6 10.47,6.5 9.84,7.14 | 9.84,7.14 IC4.28 | C9.1 21.8,21 R10.1 | R13.2 R16.2 | SV2.2 21.9,41.75 C11.1 | v22.54,35.08 21.9,35.71 C11.1 | C11.1 | 53.34,16.03 v53.34,13.17 | v51.75,17.61 53.34,16.03 | 53.34,16.03 54.29,16.98
  Top 0.61: v7.93,25.23 7.93,27.14 | v54.6,25.55 54.6,30.32 54.29,30.63 v54.29,35.08
  Top 0.813: MMC1.4 54.23,35.13 v54.29,35.08 | v70.16,24.92 76.2,24.92 78.73,22.38 C21.+ C3.+ | C3.+ 84.74,18.23 | 84.77,18.25 R11.2 | IC2.2 93.34,15.39 92.07,14.12 92.07,12.85 | 92.07,12.85 91.78,12.56 D2.A | 92.07,12.85 91.75,12.54 88.9,12.54 88.26,13.17 R2.2 85.08,14.76 83.5,16.34 C3.+
  Bottom 0.305: 71.12,24.92 C6.2 | C2.1 | 68.89,24.92 C10.1 | 73.02,24.92 IC3.16 | IC1.17 46.03,23.33 47.3,23.33 49.21,25.23 49.84,25.23 50.79,24.28 51.94,24.28 IC1.27 52.65,24.92 52.7,24.92 53.34,25.55 v54.6,25.55 | IC1.5 46.58,16.66 v47.62,16.66 | IC1.38 52.88,17.61 v51.75,17.61 v51.75,22.06
  Bottom 0.406: v28.25,2.69 25.71,2.69 24.44,3.96 v19.68,3.96 16.19,3.96 v12.38,7.77 | SV1.17 50.79,6.5 53.97,9.36 53.97,12.54 v53.34,13.17
  Bottom 0.61: 73.02,24.92 71.12,24.92 v70.16,24.92 68.89,24.92 65.72,24.92 63.81,26.82 63.81,34.44 63.18,35.08 v54.29,35.08 v30.16,35.08 v22.54,35.08 20,32.54 L1.2 18.73,26.19 13.65,26.19 12.06,24.6 8.57,24.6 v7.93,25.23
  Bottom 0.813: IC2.2 C2.1

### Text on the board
Top: V1.2 | www.ulrichradig.de
tPlace: RX = TX; RX x TX
tStop: www.ulrichradig.de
